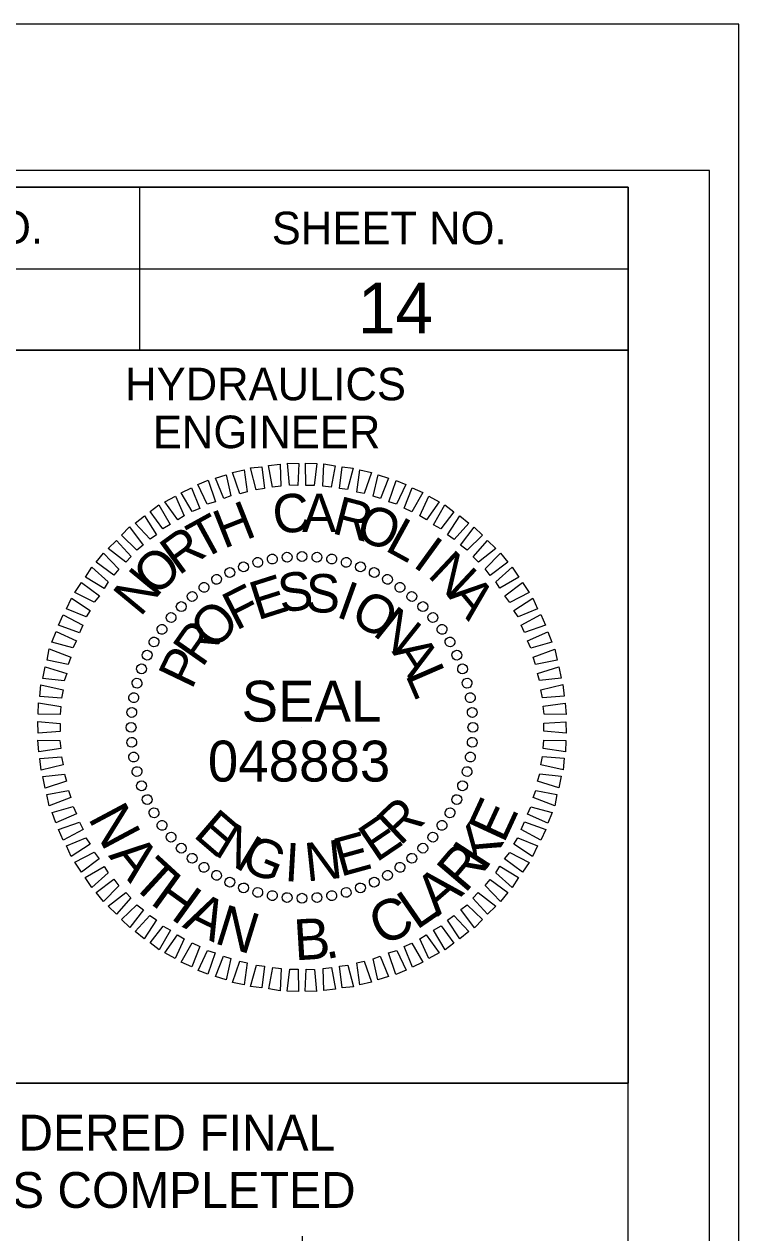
# Model space of a CAD drawing. Extents: x 1648862 to 1650855, y 808691 to 809791.
# Drawn here: x 1650436.6 to 1650546.3, y 809605.5 to 809791 of the extents above; entities that cross this region are included whole.
import ezdxf

# ---------------------------------------------------------------- set-up
doc = ezdxf.new("R2010")
doc.units = 0
for name, color, linetype in [('Default', 7, 'Continuous'), ('Old_Level_2', 7, 'Continuous'), ('Sheet Cutting Line CELL', 7, 'Continuous'), ('Sheet Data Field CELL', 7, 'Continuous'), ('Sheet Plot Border Inside CELL', 7, 'Continuous'), ('Sheet Plot Border Outside CELL', 7, 'Continuous'), ('Sheet Profile CELL', 7, 'Continuous'), ('Sheet Profile Grid Major CELL', 7, 'Continuous'), ('Sheet Sticker Exception Certification CELL', 7, 'Continuous')]:
    doc.layers.add(name, color=color, linetype=linetype)

msp = doc.modelspace()

# ---------------------------------------------------------------- linework, layer by layer
at = {"layer": 'Old_Level_2'}
for p, q in [((1650476.94, 809709.25), (1650476.94, 809709.25)), ((1650479.24, 809709.34), (1650479.24, 809709.34)), ((1650481.55, 809709.22), (1650481.55, 809709.22)), ((1650470.22, 809707.77), (1650470.22, 809707.77)), ((1650472.41, 809708.44), (1650472.41, 809708.44)), ((1650474.7, 809708.89), (1650474.7, 809708.89)), ((1650483.8, 809708.9), (1650483.8, 809708.9)), ((1650486.01, 809708.46), (1650486.01, 809708.46)), ((1650488.21, 809707.77), (1650488.21, 809707.77)), ((1650466.13, 809705.82), (1650466.13, 809705.82)), ((1650468.15, 809706.9), (1650468.15, 809706.9)), ((1650490.32, 809706.87), (1650490.32, 809706.87)), ((1650492.38, 809705.86), (1650492.38, 809705.86)), ((1650464.16, 809704.58), (1650464.16, 809704.58)), ((1650494.28, 809704.58), (1650494.28, 809704.58)), ((1650460.66, 809701.64), (1650460.66, 809701.64)), ((1650462.35, 809703.24), (1650462.35, 809703.24)), ((1650496.14, 809703.2), (1650496.14, 809703.2)), ((1650497.79, 809701.66), (1650497.79, 809701.66)), ((1650459.12, 809699.99), (1650459.12, 809699.99)), ((1650499.38, 809699.96), (1650499.38, 809699.96)), ((1650457.74, 809698.14), (1650457.74, 809698.14)), ((1650500.72, 809698.16), (1650500.72, 809698.16)), ((1650456.46, 809696.23), (1650456.46, 809696.23)), ((1650501.96, 809696.19), (1650501.96, 809696.19)), ((1650455.45, 809694.18), (1650455.45, 809694.18)), ((1650503.04, 809694.17), (1650503.04, 809694.17)), ((1650454.55, 809692.07), (1650454.55, 809692.07)), ((1650503.91, 809692.09), (1650503.91, 809692.09)), ((1650453.85, 809689.86), (1650453.85, 809689.86)), ((1650504.58, 809689.91), (1650504.58, 809689.91)), ((1650453.42, 809687.66), (1650453.42, 809687.66)), ((1650505.04, 809687.62), (1650505.04, 809687.62)), ((1650453.1, 809685.4), (1650453.1, 809685.4)), ((1650505.39, 809685.37), (1650505.39, 809685.37)), ((1650452.98, 809683.1), (1650452.98, 809683.1)), ((1650479.23, 809683.09), (1650479.23, 809683.09)), ((1650505.48, 809683.07), (1650505.48, 809683.07)), ((1650453.07, 809680.8), (1650453.07, 809680.8)), ((1650505.37, 809680.77), (1650505.37, 809680.77)), ((1650453.42, 809678.56), (1650453.42, 809678.56)), ((1650505.04, 809678.52), (1650505.04, 809678.52)), ((1650453.88, 809676.26), (1650453.88, 809676.26)), ((1650504.61, 809676.31), (1650504.61, 809676.31)), ((1650454.55, 809674.08), (1650454.55, 809674.08)), ((1650503.92, 809674.1), (1650503.92, 809674.1)), ((1650455.42, 809672), (1650455.42, 809672)), ((1650503.01, 809672), (1650503.01, 809672)), ((1650456.5, 809669.98), (1650456.5, 809669.98)), ((1650502, 809669.94), (1650502, 809669.94)), ((1650457.74, 809668.02), (1650457.74, 809668.02)), ((1650500.73, 809668.03), (1650500.73, 809668.03)), ((1650459.08, 809666.21), (1650459.08, 809666.21)), ((1650460.68, 809664.51), (1650460.68, 809664.51)), ((1650497.81, 809664.53), (1650497.81, 809664.53)), ((1650499.35, 809666.18), (1650499.35, 809666.18)), ((1650462.32, 809662.97), (1650462.32, 809662.97)), ((1650496.11, 809662.93), (1650496.11, 809662.93)), ((1650464.18, 809661.59), (1650464.18, 809661.59)), ((1650494.3, 809661.59), (1650494.3, 809661.59)), ((1650466.08, 809660.32), (1650466.08, 809660.32)), ((1650468.14, 809659.31), (1650468.14, 809659.31)), ((1650490.32, 809659.28), (1650490.32, 809659.28)), ((1650492.34, 809660.36), (1650492.34, 809660.36)), ((1650470.25, 809658.4), (1650470.25, 809658.4)), ((1650472.46, 809657.71), (1650472.46, 809657.71)), ((1650474.66, 809657.28), (1650474.66, 809657.28)), ((1650483.76, 809657.28), (1650483.76, 809657.28)), ((1650486.05, 809657.74), (1650486.05, 809657.74)), ((1650488.24, 809658.4), (1650488.24, 809658.4)), ((1650476.92, 809656.95), (1650476.92, 809656.95)), ((1650479.22, 809656.83), (1650479.22, 809656.83)), ((1650481.52, 809656.93), (1650481.52, 809656.93))]:
    msp.add_line(p, q, dxfattribs=at)
for points in [[(1650469.71, 809718.95), (1650468.56, 809722.23), (1650470.33, 809722.62), (1650470.81, 809719.23)], [(1650472.21, 809719.57), (1650471.32, 809722.9), (1650473.04, 809723.09), (1650473.47, 809719.75)], [(1650474.72, 809719.93), (1650474.08, 809723.26), (1650475.86, 809723.5), (1650475.97, 809720.11)], [(1650477.33, 809720.24), (1650477.01, 809723.63), (1650478.73, 809723.61), (1650478.58, 809720.21)], [(1650479.84, 809720.23), (1650479.78, 809723.63), (1650481.5, 809723.6), (1650481.09, 809720.2)], [(1650482.45, 809720.12), (1650482.6, 809723.52), (1650484.34, 809723.23), (1650483.71, 809719.93)], [(1650484.97, 809719.74), (1650485.38, 809723.1), (1650487.11, 809722.86), (1650486.23, 809719.61)], [(1650487.65, 809719.21), (1650488.11, 809722.62), (1650489.9, 809722.23), (1650488.75, 809718.97)], [(1650464.67, 809717.35), (1650463.26, 809720.36), (1650464.82, 809721.01), (1650465.97, 809717.68)], [(1650467.22, 809718.23), (1650465.96, 809721.34), (1650467.57, 809721.84), (1650468.31, 809718.61)], [(1650490.17, 809718.58), (1650490.9, 809721.83), (1650492.53, 809721.34), (1650491.27, 809718.23)], [(1650492.54, 809717.68), (1650493.68, 809720.99), (1650495.16, 809720.39), (1650493.75, 809717.33)], [(1650460.16, 809714.92), (1650458.18, 809717.71), (1650459.79, 809718.57), (1650461.15, 809715.56)], [(1650462.39, 809716.21), (1650460.66, 809719.11), (1650462.27, 809719.87), (1650463.53, 809716.7)], [(1650494.91, 809716.72), (1650496.16, 809719.83), (1650497.79, 809719.13), (1650496.07, 809716.17)], [(1650497.33, 809715.56), (1650498.69, 809718.57), (1650500.28, 809717.71), (1650498.34, 809714.95)], [(1650457.89, 809713.57), (1650455.9, 809716.2), (1650457.25, 809717.22), (1650459.02, 809714.22)], [(1650499.4, 809714.19), (1650501.17, 809717.25), (1650502.55, 809716.18), (1650500.56, 809713.58)], [(1650455.93, 809711.97), (1650453.63, 809714.44), (1650455.03, 809715.56), (1650456.91, 809712.66)], [(1650501.57, 809712.66), (1650503.45, 809715.57), (1650504.83, 809714.44), (1650502.57, 809711.94)], [(1650453.86, 809710.31), (1650451.52, 809712.57), (1650452.76, 809713.85), (1650454.84, 809711.06)], [(1650503.58, 809711.07), (1650505.68, 809713.83), (1650506.96, 809712.59), (1650504.59, 809710.3)], [(1650452.17, 809708.45), (1650449.47, 809710.55), (1650450.75, 809711.77), (1650452.99, 809709.3)], [(1650505.5, 809709.27), (1650507.7, 809711.77), (1650508.98, 809710.54), (1650506.3, 809708.45)], [(1650450.37, 809706.43), (1650447.62, 809708.42), (1650448.75, 809709.8), (1650451.09, 809707.38)], [(1650507.36, 809707.42), (1650509.72, 809709.82), (1650510.85, 809708.43), (1650508.11, 809706.39)], [(1650448.84, 809704.42), (1650445.99, 809706.14), (1650446.95, 809707.68), (1650449.5, 809705.42)], [(1650508.96, 809705.41), (1650511.49, 809707.65), (1650512.51, 809706.15), (1650509.61, 809704.43)], [(1650510.36, 809703.29), (1650513.1, 809705.33), (1650514.12, 809703.78), (1650511.11, 809702.26)], [(1650447.31, 809702.3), (1650444.35, 809703.81), (1650445.37, 809705.3), (1650448.13, 809703.25)], [(1650446.09, 809700.03), (1650443.09, 809701.28), (1650443.85, 809702.92), (1650446.7, 809701.03)], [(1650511.76, 809701.02), (1650514.66, 809702.9), (1650515.36, 809701.29), (1650512.41, 809700.03)], [(1650445.09, 809697.6), (1650441.83, 809698.75), (1650442.58, 809700.38), (1650445.59, 809698.76)], [(1650512.85, 809698.79), (1650515.9, 809700.41), (1650516.61, 809698.75), (1650513.39, 809697.65)], [(1650444.08, 809695.29), (1650440.83, 809696.17), (1650441.48, 809697.8), (1650444.64, 809696.39)], [(1650513.83, 809696.35), (1650516.99, 809697.76), (1650517.6, 809696.15), (1650514.37, 809695.26)], [(1650443.34, 809692.76), (1650440.09, 809693.39), (1650440.43, 809695.12), (1650443.74, 809693.87)], [(1650514.71, 809693.85), (1650518.03, 809695.11), (1650518.38, 809693.39), (1650515.09, 809692.76)], [(1650442.71, 809690.24), (1650439.46, 809690.6), (1650439.79, 809692.39), (1650443.11, 809691.35)], [(1650515.38, 809691.35), (1650518.66, 809692.4), (1650519, 809690.63), (1650515.71, 809690.26)], [(1650442.34, 809687.57), (1650438.99, 809687.82), (1650439.16, 809689.6), (1650442.58, 809688.83)], [(1650515.89, 809688.85), (1650519.28, 809689.64), (1650519.47, 809687.87), (1650516.13, 809687.6)], [(1650442.12, 809685.05), (1650438.72, 809685.1), (1650438.79, 809686.83), (1650442.2, 809686.31)], [(1650516.25, 809686.35), (1650519.64, 809686.82), (1650519.78, 809685.05), (1650516.38, 809685.09)], [(1650442.11, 809682.44), (1650438.72, 809682.22), (1650438.69, 809684), (1650442.09, 809683.69)], [(1650516.35, 809683.73), (1650519.75, 809683.95), (1650519.78, 809682.17), (1650516.37, 809682.48)], [(1650442.21, 809679.83), (1650438.82, 809679.35), (1650438.68, 809681.12), (1650442.08, 809681.08)], [(1650516.34, 809681.12), (1650519.74, 809681.07), (1650519.67, 809679.35), (1650516.26, 809679.86)], [(1650442.57, 809677.32), (1650439.18, 809676.53), (1650438.99, 809678.3), (1650442.34, 809678.57)], [(1650516.13, 809678.61), (1650519.48, 809678.35), (1650519.3, 809676.57), (1650515.89, 809677.35)], [(1650443.08, 809674.82), (1650439.81, 809673.77), (1650439.46, 809675.54), (1650442.75, 809675.91)], [(1650515.75, 809675.93), (1650519, 809675.57), (1650518.67, 809673.79), (1650515.36, 809674.83)], [(1650443.75, 809672.32), (1650440.43, 809671.06), (1650440.08, 809672.78), (1650443.37, 809673.41)], [(1650515.12, 809673.41), (1650518.37, 809672.79), (1650518.04, 809671.06), (1650514.72, 809672.31)], [(1650444.63, 809669.83), (1650441.47, 809668.41), (1650440.86, 809670.02), (1650444.09, 809670.92)], [(1650514.38, 809670.89), (1650517.64, 809670), (1650516.98, 809668.37), (1650513.82, 809669.78)], [(1650445.62, 809667.39), (1650442.56, 809665.76), (1650441.85, 809667.42), (1650445.07, 809668.53)], [(1650513.37, 809668.57), (1650516.64, 809667.42), (1650515.88, 809665.79), (1650512.87, 809667.41)], [(1650446.7, 809665.16), (1650443.81, 809663.28), (1650443.1, 809664.88), (1650446.06, 809666.14)], [(1650512.37, 809666.15), (1650515.37, 809664.89), (1650514.62, 809663.26), (1650511.76, 809665.14)], [(1650448.1, 809662.88), (1650445.37, 809660.84), (1650444.34, 809662.4), (1650447.35, 809663.91)], [(1650511.15, 809663.88), (1650514.11, 809662.36), (1650513.09, 809660.88), (1650510.33, 809662.92)], [(1650449.5, 809660.76), (1650446.97, 809658.52), (1650445.96, 809660.02), (1650448.85, 809661.74)], [(1650509.62, 809661.76), (1650512.48, 809660.03), (1650511.51, 809658.5), (1650508.96, 809660.75)], [(1650451.1, 809658.75), (1650448.74, 809656.35), (1650447.62, 809657.75), (1650450.35, 809659.78)], [(1650508.09, 809659.74), (1650510.84, 809657.75), (1650509.72, 809656.37), (1650507.37, 809658.79)], [(1650452.97, 809656.9), (1650450.76, 809654.4), (1650449.48, 809655.63), (1650452.17, 809657.72)], [(1650506.29, 809657.72), (1650509, 809655.63), (1650507.71, 809654.4), (1650505.47, 809656.87)], [(1650454.88, 809655.1), (1650452.78, 809652.35), (1650451.51, 809653.58), (1650453.87, 809655.87)], [(1650504.6, 809655.86), (1650506.94, 809653.6), (1650505.71, 809652.33), (1650503.62, 809655.12)], [(1650456.89, 809653.52), (1650455.01, 809650.61), (1650453.63, 809651.73), (1650455.89, 809654.23)], [(1650502.54, 809654.21), (1650504.83, 809651.74), (1650503.44, 809650.61), (1650501.56, 809653.51)], [(1650459.06, 809651.98), (1650457.29, 809648.92), (1650455.91, 809649.99), (1650457.9, 809652.59)], [(1650500.58, 809652.6), (1650502.56, 809649.97), (1650501.22, 809648.95), (1650499.44, 809651.96)], [(1650461.13, 809650.61), (1650459.77, 809647.6), (1650458.18, 809648.46), (1650460.12, 809651.22)], [(1650463.55, 809649.45), (1650462.3, 809646.34), (1650460.67, 809647.04), (1650462.39, 809650)], [(1650496.07, 809649.96), (1650497.8, 809647.06), (1650496.19, 809646.3), (1650494.93, 809649.47)], [(1650498.3, 809651.26), (1650500.28, 809648.47), (1650498.68, 809647.6), (1650497.32, 809650.61)], [(1650465.92, 809648.5), (1650464.78, 809645.18), (1650463.3, 809645.78), (1650464.72, 809648.84)], [(1650468.29, 809647.6), (1650467.57, 809644.34), (1650465.94, 809644.83), (1650467.19, 809647.94)], [(1650491.25, 809647.94), (1650492.5, 809644.83), (1650490.89, 809644.33), (1650490.15, 809647.56)], [(1650493.79, 809648.82), (1650495.2, 809645.82), (1650493.65, 809645.16), (1650492.49, 809648.49)], [(1650470.81, 809646.96), (1650470.35, 809643.55), (1650468.57, 809643.94), (1650469.71, 809647.2)], [(1650473.49, 809646.43), (1650473.08, 809643.08), (1650471.35, 809643.31), (1650472.23, 809646.57)], [(1650476.01, 809646.06), (1650475.86, 809642.65), (1650474.13, 809642.94), (1650474.75, 809646.24)], [(1650478.62, 809645.95), (1650478.68, 809642.55), (1650476.96, 809642.57), (1650477.37, 809645.98)], [(1650481.13, 809645.94), (1650481.46, 809642.54), (1650479.73, 809642.57), (1650479.88, 809645.97)], [(1650483.74, 809646.24), (1650484.38, 809642.91), (1650482.6, 809642.67), (1650482.49, 809646.07)], [(1650486.25, 809646.6), (1650487.14, 809643.27), (1650485.42, 809643.08), (1650485, 809646.42)], [(1650488.75, 809647.22), (1650489.9, 809643.95), (1650488.13, 809643.55), (1650487.65, 809646.94)]]:
    msp.add_lwpolyline(points, close=True, dxfattribs=at)
for centre, major_axis in [((1650472.44, 809708.42), (-0.195, 0.727)), ((1650474.68, 809708.92), (-0.131, 0.742)), ((1650476.95, 809709.21), (-0.066, 0.75)), ((1650479.23, 809709.31), (0, 0.753)), ((1650481.52, 809709.21), (0.066, 0.75)), ((1650483.79, 809708.92), (0.131, 0.742)), ((1650486.02, 809708.42), (0.195, 0.727)), ((1650468.15, 809706.86), (-0.318, 0.682)), ((1650470.26, 809707.73), (-0.258, 0.708)), ((1650488.2, 809707.73), (0.258, 0.708)), ((1650490.32, 809706.86), (0.318, 0.682)), ((1650464.19, 809704.57), (-0.432, 0.617)), ((1650466.12, 809705.8), (-0.376, 0.652)), ((1650492.35, 809705.8), (0.376, 0.652)), ((1650494.27, 809704.57), (0.432, 0.617)), ((1650462.37, 809703.18), (-0.484, 0.577)), ((1650496.09, 809703.18), (0.484, 0.577)), ((1650460.69, 809701.63), (-0.532, 0.532)), ((1650497.78, 809701.63), (0.532, 0.532)), ((1650459.14, 809699.95), (-0.577, 0.484)), ((1650499.32, 809699.95), (0.577, 0.484)), ((1650457.75, 809698.13), (-0.617, 0.432)), ((1650500.72, 809698.13), (0.617, 0.432)), ((1650456.52, 809696.2), (-0.652, 0.376)), ((1650501.95, 809696.2), (0.652, 0.376)), ((1650455.46, 809694.17), (-0.682, 0.318)), ((1650503, 809694.17), (0.682, 0.318)), ((1650454.59, 809692.06), (-0.708, 0.258)), ((1650503.88, 809692.06), (0.708, 0.258)), ((1650453.9, 809689.87), (-0.727, 0.195)), ((1650504.57, 809689.87), (0.727, 0.195)), ((1650453.4, 809687.64), (-0.742, 0.131)), ((1650505.06, 809687.64), (0.742, 0.131)), ((1650453.1, 809685.37), (-0.75, 0.066)), ((1650505.36, 809685.37), (0.75, 0.066)), ((1650453, 809683.09), (-0.753, 0)), ((1650505.46, 809683.09), (0.753, 0)), ((1650453.1, 809680.8), (-0.75, -0.066)), ((1650505.36, 809680.8), (0.75, -0.066)), ((1650453.4, 809678.53), (-0.742, -0.131)), ((1650505.06, 809678.53), (0.742, -0.131)), ((1650453.9, 809676.3), (-0.727, -0.195)), ((1650504.57, 809676.3), (0.727, -0.195)), ((1650454.59, 809674.12), (-0.708, -0.258)), ((1650503.88, 809674.12), (0.708, -0.258)), ((1650455.46, 809672), (-0.682, -0.318)), ((1650503, 809672), (0.682, -0.318)), ((1650456.52, 809669.97), (-0.652, -0.376)), ((1650501.95, 809669.97), (0.652, -0.376)), ((1650457.75, 809668.04), (-0.617, -0.432)), ((1650500.72, 809668.04), (0.617, -0.432)), ((1650459.14, 809666.23), (-0.577, -0.484)), ((1650499.32, 809666.23), (0.577, -0.484)), ((1650460.69, 809664.54), (-0.532, -0.532)), ((1650497.78, 809664.54), (0.532, -0.532)), ((1650462.37, 809662.99), (-0.484, -0.577)), ((1650496.09, 809662.99), (0.484, -0.577)), ((1650464.19, 809661.6), (-0.432, -0.617)), ((1650466.12, 809660.37), (-0.376, -0.652)), ((1650492.35, 809660.37), (0.376, -0.652)), ((1650494.27, 809661.6), (0.432, -0.617)), ((1650468.15, 809659.32), (-0.318, -0.682)), ((1650470.26, 809658.44), (-0.258, -0.708)), ((1650488.2, 809658.44), (0.258, -0.708)), ((1650490.32, 809659.32), (0.318, -0.682)), ((1650472.44, 809657.75), (-0.195, -0.727)), ((1650474.68, 809657.26), (-0.131, -0.742)), ((1650476.95, 809656.96), (-0.066, -0.75)), ((1650479.23, 809656.86), (0, -0.753)), ((1650481.52, 809656.96), (0.066, -0.75)), ((1650483.79, 809657.26), (0.131, -0.742)), ((1650486.02, 809657.75), (0.195, -0.727))]:
    msp.add_ellipse(centre, major_axis=major_axis, ratio=0.999708, dxfattribs=at)
at = {"layer": 'Sheet Cutting Line CELL'}
msp.add_line((1650546.28, 809791.02), (1648862.28, 809791.02), dxfattribs=at)
at = {"layer": 'Sheet Plot Border Inside CELL'}
msp.add_lwpolyline([(1648875.28, 808713.47), (1650541.78, 808713.47), (1650541.78, 809768.57), (1648875.28, 809768.57)], close=True, dxfattribs=at)
at = {"layer": 'Sheet Plot Border Outside CELL'}
msp.add_lwpolyline([(1648862.28, 808691.02), (1650546.28, 808691.02), (1650546.28, 809791.02), (1648862.28, 809791.02)], close=True, dxfattribs=at)
at = {"layer": 'Sheet Profile CELL'}
for p, q in [((1650454.28, 809765.97), (1650454.28, 809740.97)), ((1650329.23, 809753.47), (1650529.28, 809753.47))]:
    msp.add_line(p, q, dxfattribs=at)
for points in [[(1650529.28, 809766.02), (1649029.28, 809766.02), (1649029.28, 808716.02), (1650529.28, 808716.02)], [(1650329.23, 809766.02), (1650529.28, 809766.02), (1650529.28, 809740.97), (1650329.23, 809740.97)], [(1650429.28, 809740.97), (1650529.28, 809740.97), (1650529.28, 809628.47), (1650429.28, 809628.47)]]:
    msp.add_lwpolyline(points, close=True, dxfattribs=at)
at = {"layer": 'Sheet Profile Grid Major CELL'}
msp.add_lwpolyline([(1650479.28, 809604.97), (1650479.28, 809266.02), (1650529.28, 809266.02), (1650529.28, 809616.02)], dxfattribs=at)
at = {"layer": 'Sheet Sticker Exception Certification CELL'}
for p, q in [((1650329.23, 809628.47), (1650529.27, 809628.47)), ((1650329.23, 809628.47), (1650529.27, 809628.47)), ((1650529.27, 809628.46), (1650529.27, 809604.96)), ((1650529.27, 809628.46), (1650529.27, 809604.96))]:
    msp.add_line(p, q, dxfattribs=at)

# ---------------------------------------------------------------- texts
at = {"layer": 'Default'}
for s, rotation, p in [('E', 65.2198, (1650510.2, 809665.13)), ('N', 298.0773, (1650446.31, 809669.19)), ('K', 57.024, (1650507.33, 809660.9)), ('A', 308.6891, (1650449.42, 809663.36)), ('R', 49.6233, (1650504.25, 809657.47)), ('T', 317.4354, (1650452.76, 809659.05)), ('H', 324.1633, (1650455.75, 809656.11)), ('A', 40.877, (1650500.07, 809653.97)), ('A', 334.0411, (1650460.72, 809652.48)), ('L', 34.6689, (1650496.8, 809651.89)), ('N', 342.7874, (1650465.58, 809650.01)), ('C', 25.1886, (1650491.43, 809649.42)), ('B', 3.4911, (1650478.14, 809647.31)), ('.', 11.1059, (1650482.89, 809647.47))]:
    msp.add_text(s, height=6.27, rotation=rotation, dxfattribs=at).set_placement(p)
at = {"layer": 'Old_Level_2'}
for s, rotation, p in [('C', 7.2199, (1650475.11, 809712.67)), ('A', 0.0203, (1650479.23, 809713.05)), ('R', 345.6211, (1650483.63, 809712.92)), ('H', 21.6195, (1650467.2, 809710.44)), ('O', 338.4212, (1650487.14, 809712.2)), ('T', 28.8198, (1650463.83, 809708.65)), ('L', 331.2209, (1650491.78, 809710.34)), ('R', 36.0205, (1650460.31, 809706.29)), ('I', 324.0201, (1650496.06, 809707.91)), ('O', 43.2217, (1650456.76, 809702.99)), ('N', 316.8189, (1650498.33, 809706.33)), ('N', 50.4235, (1650454.41, 809699.91)), ('E', 17.6111, (1650472.41, 809699.49)), ('S', 8.2556, (1650476, 809700.65)), ('S', 358.9004, (1650479.76, 809700.77)), ('I', 340.1896, (1650484.27, 809700.12)), ('A', 309.6172, (1650501.47, 809703.29)), ('F', 26.967, (1650469.09, 809697.87)), ('O', 330.8335, (1650486.37, 809699.42)), ('O', 45.6812, (1650465.69, 809694.72)), ('N', 321.4766, (1650489.91, 809697.39)), ('R', 55.0397, (1650463.91, 809692.13)), ('A', 302.7603, (1650492.94, 809694.73)), ('P', 64.3989, (1650462.29, 809688.75)), ('L', 293.4009, (1650495.04, 809691.15)), ('R', 43.4814, (1650494.3, 809664.78)), ('E', 319.2769, (1650462.37, 809666.42)), ('N', 328.634, (1650465.56, 809663.65)), ('E', 34.1241, (1650490.63, 809662.26)), ('E', 15.4118, (1650485.12, 809660.13)), ('G', 337.9902, (1650469.57, 809661.37)), ('I', 356.7012, (1650476.45, 809659.5)), ('N', 6.0564, (1650479.96, 809659.41))]:
    msp.add_text(s, height=5.9, rotation=rotation, dxfattribs=at).set_placement(p)
for s, height, p in [('SEAL', 6.273, (1650469.96, 809683.97)), ('048883', 6.275, (1650464.78, 809674.77))]:
    msp.add_text(s, height=height, dxfattribs=at).set_placement(p)
at = {"layer": 'Sheet Data Field CELL'}
msp.add_text('14', height=7.75, dxfattribs=at).set_placement((1650487.82, 809743.57))
at = {"layer": 'Sheet Profile CELL'}
for s, height, p in [('PROJECT REFERENCE NO.', 5.0001, (1650351.44, 809757.34)), ('SHEET NO.', 5, (1650474.59, 809757.24)), ('HYDRAULICS', 5, (1650452.09, 809733.29)), ('ENGINEER', 5, (1650456.34, 809725.94))]:
    msp.add_text(s, height=height, dxfattribs=at).set_placement(p)
at = {"layer": 'Sheet Sticker Exception Certification CELL'}
for s, p in [('DOCUMENT NOT CONSIDERED FINAL', (1650350.3, 809618.13)), ('DOCUMENT NOT CONSIDERED FINAL', (1650350.3, 809618.13)), ('UNLESS ALL SIGNATURES COMPLETED', (1650345.23, 809609.33)), ('UNLESS ALL SIGNATURES COMPLETED', (1650345.23, 809609.33))]:
    msp.add_text(s, height=5.5, dxfattribs=at).set_placement(p)

doc.saveas('drawing.dxf')
